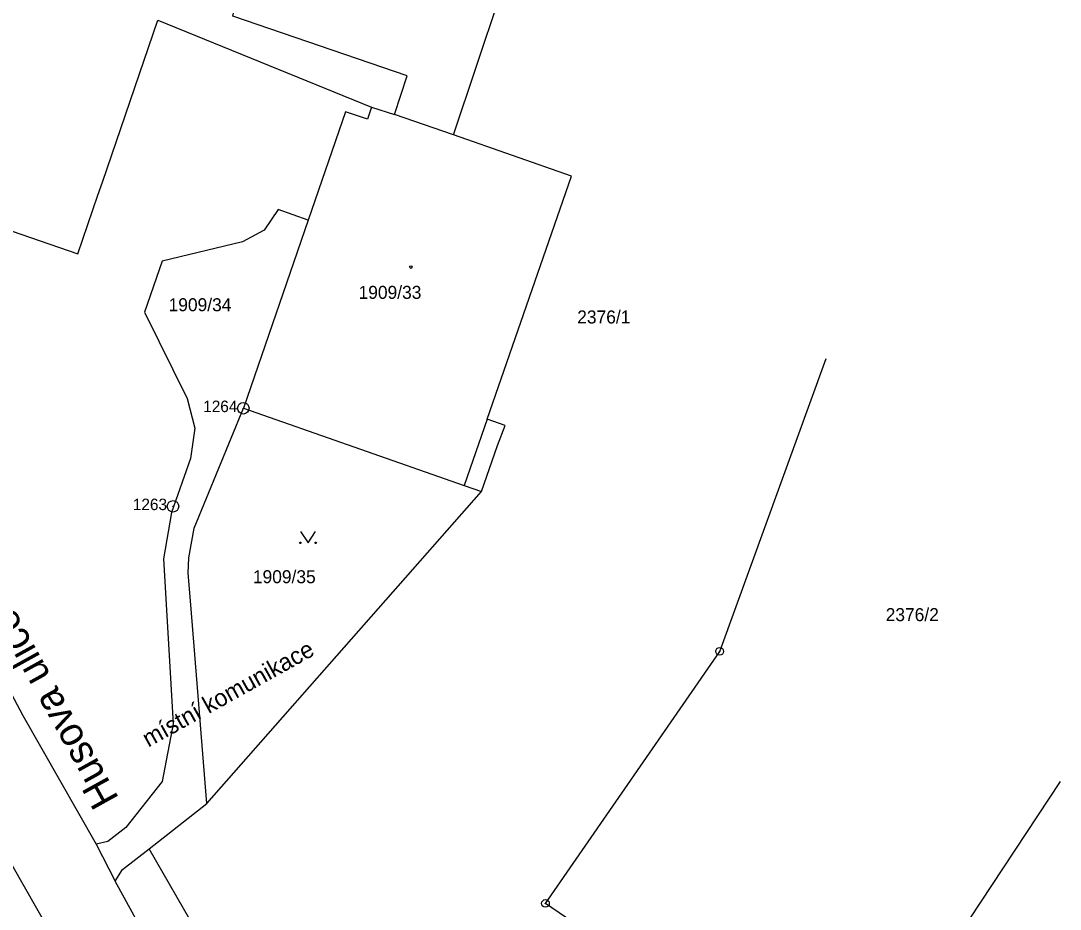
# Model space of a CAD drawing. Extents: x -483721 to -481876, y -1129170 to -1127366.
# Drawn here: x -482277 to -482141.1, y -1128127.3 to -1128011.1 of the extents above; entities that cross this region are included whole.
import ezdxf

# ---------------------------------------------------------------- set-up
doc = ezdxf.new("R2010")
doc.units = 0
for name, color, linetype in [('Hranice parcel', 7, 'Continuous'), ('Parcelní čísla', 7, 'Continuous'), ('u_sil_popis', 7, 'Continuous'), ('Vnitřní kresba', 7, 'Continuous'), ('x_legenda', 7, 'Continuous'), ('Značky bodu BP', 7, 'Continuous'), ('Značky budov', 7, 'Continuous'), ('Značky kultur', 7, 'Continuous')]:
    doc.layers.add(name, color=color, linetype=linetype)

msp = doc.modelspace()

# ---------------------------------------------------------------- linework, layer by layer
at = {"layer": 'Hranice parcel'}
for p, q in [((-482220.41, -1128026), (-482208.15, -1127989.34)), ((-482231.12, -1128022.34), (-482228.13, -1128023.31)), ((-482220.41, -1128026), (-482228.13, -1128023.31)), ((-482239.42, -1128037.16), (-482243.33, -1128035.76)), ((-482239.42, -1128037.16), (-482247.85, -1128061.71)), ((-482258.5, -1128042.49), (-482260.79, -1128049.15)), ((-482252.67, -1128113.45), (-482216.76, -1128072.64)), ((-482257.27, -1128075.39), (-482258.33, -1128081.43)), ((-482260.19, -1128119.34), (-482252.67, -1128113.45)), ((-482265.6, -1128118.39), (-482267.12, -1128118.74)), ((-482267.12, -1128118.74), (-482264.66, -1128123.59)), ((-482228.12, -1128175.02), (-482260.19, -1128119.34)), ((-482214.43, -1128213.98), (-482264.66, -1128123.59))]:
    msp.add_line(p, q, dxfattribs=at)
for points in [[(-482286.79, -1127956.55), (-482287.8, -1127959.57), (-482296.54, -1127984.93), (-482298.01, -1127989.31), (-482295.34, -1128007.4), (-482292.28, -1128008.42), (-482288.47, -1128009.67), (-482283.87, -1127996.64), (-482275.84, -1127999.4), (-482288.12, -1128035.12), (-482269.53, -1128041.52), (-482266.9, -1128033.86), (-482266.32, -1128032.16), (-482259.05, -1128010.98), (-482231.12, -1128022.34)], [(-482228.13, -1128023.31), (-482226.45, -1128018.27), (-482249.24, -1128010.47), (-482249.01, -1128009.28), (-482257.37, -1128006.26), (-482246.97, -1127975.8), (-482255.43, -1127972.83), (-482255.11, -1127971.92), (-482256.79, -1127971.28), (-482257.09, -1127972.26), (-482265.55, -1127969.29), (-482273.31, -1127992.1), (-482279.97, -1127989.71), (-482271.98, -1127967.11), (-482271.81, -1127966.37), (-482270.44, -1127962.27), (-482286.79, -1127956.55)], [(-482345.11, -1127966.35), (-482338.74, -1127977.4), (-482305.64, -1128034.82), (-482303.71, -1128038.3), (-482284.85, -1128071.44), (-482287.27, -1128073.4), (-482288.88, -1128074.62), (-482290.67, -1128075.58), (-482288.73, -1128079.35), (-482276.7, -1128101.91), (-482267.12, -1128118.74)], [(-482364.93, -1127969.05), (-482343.84, -1128006.04), (-482234.22, -1128198.65), (-482215.31, -1128236.66), (-482200.01, -1128286.72)], [(-482231.12, -1128022.34), (-482231.67, -1128023.94), (-482234.51, -1128022.95), (-482239.42, -1128037.16)], [(-482216.76, -1128072.64), (-482214.66, -1128066.6), (-482213.63, -1128063.99), (-482215.99, -1128063.17), (-482204.99, -1128031.38), (-482220.41, -1128026)], [(-482243.33, -1128035.76), (-482245.14, -1128038.45), (-482248, -1128039.96), (-482258.5, -1128042.49)], [(-482260.79, -1128049.15), (-482255.24, -1128060.45), (-482254.22, -1128064.33), (-482254.78, -1128068.3), (-482257.27, -1128075.39)], [(-482192.81, -1128137.16), (-482208.38, -1128126.5), (-482185.6, -1128093.53), (-482171.69, -1128055.23)], [(-482252.67, -1128113.45), (-482254.76, -1128087.44), (-482255.09, -1128083.31), (-482254.99, -1128081.3), (-482254.32, -1128077.43), (-482247.85, -1128061.71)], [(-482247.85, -1128061.71), (-482218.99, -1128071.82), (-482216.76, -1128072.64)], [(-482258.33, -1128081.43), (-482257.07, -1128103), (-482258.48, -1128110.55), (-482263.25, -1128116.57), (-482265.6, -1128118.39)], [(-482141.08, -1128110.56), (-482164.86, -1128146.61)], [(-482264.66, -1128123.59), (-482263.69, -1128122.08), (-482260.19, -1128119.34)]]:
    msp.add_lwpolyline(points, dxfattribs=at)
at = {"layer": 'Vnitřní kresba'}
msp.add_line((-482215.99, -1128063.17), (-482218.99, -1128071.82), dxfattribs=at)
at = {"layer": 'Značky bodu BP'}
for centre, radius in [((-482247.88, -1128061.74), 0.75), ((-482247.88, -1128061.74), 0.03), ((-482257.08, -1128074.56), 0.75), ((-482257.08, -1128074.56), 0.03), ((-482185.6, -1128093.53), 0.5), ((-482185.6, -1128093.53), 0.0303), ((-482208.38, -1128126.5), 0.5), ((-482208.38, -1128126.5), 0.0303)]:
    msp.add_circle(centre, radius, dxfattribs=at)
at = {"layer": 'Značky budov'}
msp.add_circle((-482225.97, -1128043.27), 0.175, dxfattribs=at)
at = {"layer": 'Značky kultur'}
msp.add_lwpolyline([(-482240.43, -1128077.84), (-482239.43, -1128079.34), (-482238.43, -1128077.84)], dxfattribs=at)
for centre in [(-482240.43, -1128079.34), (-482238.43, -1128079.34)]:
    msp.add_circle(centre, 0.1, dxfattribs=at)

# ---------------------------------------------------------------- texts
at = {"layer": 'Parcelní čísla'}
for s, p in [('1909/33', (-482232.82, -1128047.43)), ('1909/34', (-482257.66, -1128049.05)), ('2376/1', (-482204.23, -1128050.65)), ('1909/35', (-482246.64, -1128084.62)), ('2376/2', (-482163.9, -1128089.58))]:
    msp.add_text(s, height=1.7, dxfattribs=at).set_placement(p)
at = {"layer": 'u_sil_popis'}
msp.add_text('Husova ulice', height=3.75, rotation=118.9729, dxfattribs=at).set_placement((-482264.09, -1128112.78))
at = {"layer": 'x_legenda'}
msp.add_text('místní komunikace', height=2.25, rotation=29.0987, dxfattribs=at).set_placement((-482260.31, -1128106.13))
at = {"layer": 'Značky bodu BP'}
for s, p in [('1264', (-482253.13, -1128062.24)), ('1263', (-482262.33, -1128075.06))]:
    msp.add_text(s, height=1.5, dxfattribs=at).set_placement(p)

doc.saveas('drawing.dxf')
